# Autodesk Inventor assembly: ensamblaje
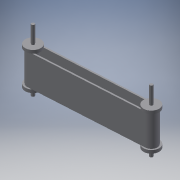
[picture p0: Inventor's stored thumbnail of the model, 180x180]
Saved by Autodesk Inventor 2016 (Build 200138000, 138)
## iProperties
Created: 2016-06
Part Number: ensamblaje
Material: Genérico
Document SubType Name: Assembly
Designer: adm
Author: adm
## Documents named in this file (5)
- C:\Users\adm\Desktop\Alvarez\ensamblaje.iam
- C:\Users\adm\Desktop\Alvarez\eje x2.ipt
- C:\Users\adm\Desktop\Alvarez\cilindro de movimientox2.ipt
- C:\Users\adm\Desktop\Alvarez\rueda del eje(sin movimiento)x4.ipt
- C:\Users\adm\Desktop\Alvarez\faja.ipt
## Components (9 placed, 4 different names)
1. eje x2:1 — Ángulo:1, Tangente:2, Nivelación:1, Tangente:5, Tangente:6, Ángulo:2
2. eje x2:2 — Ángulo:1, Nivelación:1, Coincidencia:5, Tangente:7, Coincidencia:7, Ángulo:3
3. cilindro de movimientox2:1 — Tangente:7, Coincidencia:9, Coincidencia:10, Coincidencia:11, Tangente:8
4. cilindro de movimientox2:2 — Tangente:2, Coincidencia:3, Coincidencia:4, Tangente:9
5. rueda del eje(sin movimiento)x4:1 — Tangente:6, Coincidencia:3, Coincidencia:13
6. rueda del eje(sin movimiento)x4:2 — Coincidencia:5, Coincidencia:11
7. rueda del eje(sin movimiento)x4:3 — Tangente:5, Coincidencia:4, Ángulo:2
8. rueda del eje(sin movimiento)x4:4 — Coincidencia:7, Coincidencia:9, Coincidencia:10, Coincidencia:12
9. faja:1 — Tangente:8, Ángulo:3, Coincidencia:12, Tangente:9, Coincidencia:13
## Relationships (19: Mate 9, Tangent 6, Angle 3, Flush 1)
- Ángulo:1 [Angle]: eje x2:1 ↔ eje x2:2
- Tangente:2: eje x2:1 ↔ cilindro de movimientox2:2
- Nivelación:1 [Flush]: eje x2:1 ↔ eje x2:2
- Tangente:5: eje x2:1 ↔ rueda del eje(sin movimiento)x4:3
- Tangente:6: eje x2:1 ↔ rueda del eje(sin movimiento)x4:1
- Coincidencia:3 [Mate]: cilindro de movimientox2:2 ↔ rueda del eje(sin movimiento)x4:1
- Coincidencia:4 [Mate]: cilindro de movimientox2:2 ↔ rueda del eje(sin movimiento)x4:3
- Ángulo:2 [Angle]: eje x2:1 ↔ rueda del eje(sin movimiento)x4:3
- Coincidencia:5 [Mate]: eje x2:2 ↔ rueda del eje(sin movimiento)x4:2
- Tangente:7: eje x2:2 ↔ cilindro de movimientox2:1
- Coincidencia:7 [Mate]: eje x2:2 ↔ rueda del eje(sin movimiento)x4:4
- Coincidencia:9 [Mate]: cilindro de movimientox2:1 ↔ rueda del eje(sin movimiento)x4:4
- Coincidencia:10 [Mate]: cilindro de movimientox2:1 ↔ rueda del eje(sin movimiento)x4:4
- Coincidencia:11 [Mate]: cilindro de movimientox2:1 ↔ rueda del eje(sin movimiento)x4:2
- Tangente:8: cilindro de movimientox2:1 ↔ faja:1
- Ángulo:3 [Angle]: eje x2:2 ↔ faja:1
- Coincidencia:12 [Mate]: rueda del eje(sin movimiento)x4:4 ↔ faja:1
- Tangente:9: cilindro de movimientox2:2 ↔ faja:1
- Coincidencia:13 [Mate]: rueda del eje(sin movimiento)x4:1 ↔ faja:1
